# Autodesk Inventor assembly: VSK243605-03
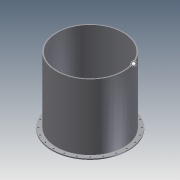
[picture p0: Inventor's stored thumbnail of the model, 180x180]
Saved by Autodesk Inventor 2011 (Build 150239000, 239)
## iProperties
Created: 2010-06
Part Number: VSK243605-03
Document SubType Name: Assembly
Designer: mklassen
OD: 36.000 in
THK: 0.625 in
SKVOFS: -6.000 in
SKLEN: 3.000 ft
BHN: 24.000 ul
Author: mklassen
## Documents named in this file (3)
- O:\cadd\tutorials\inventor 2011\iLogic\VSK243605-03.iam
- O:\cadd\tutorials\inventor 2011\iLogic\Skirt-01-02.ipt
- O:\cadd\tutorials\inventor 2011\iLogic\SkirtFlange-01-02.ipt
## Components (2 placed, 2 different names)
1. Skirt-01:1 — Flush:1, Flush:2, Flush:3
2. SkirtFlange-01:1 — Flush:4, Flush:5
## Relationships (5: Flush 5)
- Flush:1: Skirt-01:1
- Flush:2: Skirt-01:1
- Flush:3: Skirt-01:1
- Flush:4: SkirtFlange-01:1
- Flush:5: SkirtFlange-01:1
